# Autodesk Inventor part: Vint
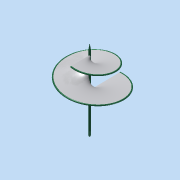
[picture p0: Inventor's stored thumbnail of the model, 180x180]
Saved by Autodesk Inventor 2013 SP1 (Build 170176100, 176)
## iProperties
Created: 2016-04
Part Number: Vint
Material: Пластик АБС
Document SubType Name: Modeling
Designer: Кравец
Density: 1 g/cm^3
Author: Кравец
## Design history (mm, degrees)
sketch "Эскиз1"
  geometry: L1 (0, 0)-(0, 70)
  constraints: 2 end point, 1 vertical
  dimensions: "d0" = 70 distance of L1.start L1.end
node "3D-эскиз3"
sketch "3D-эскиз4"
feature "Участок поверхности1" sketch "3D-эскиз4" dims "d17" = 0
feature "Толщина1" dims "d18" = 1, "d19" = 1
sketch "Эскиз2"
  geometry: L1 (0, 0)-(0, 80); L2 (-45, 80)-(-75, 0); L3 (-75, 0)-(-101.109, 0); L4 (-101.109, 0)-(-101.996, 80); L5 (-101.996, 80)-(-45, 80)
  constraints: 10 end point, 2 horizontal, 2 point on line, 1 vertical
  dimensions: "d20" = 80 vertical distance of L3.end L4.end; "d22" = 150 diameter of L2.end L1; "d23" = 90 diameter of L2.start L1
revolve "Вращение1" sketch "Эскиз2" stored, may be unused: angle "d24" = 90 deg
node "РабПлоскость1"
sketch "Эскиз3"
  geometry: C1 r 1.5 at (0, 0); 1 further point
  constraints: 1 centre point
  dimensions: "d25" = 3 diameter of C1
sketch "3D-эскиз5"
feature "Сдвиг1" sketch "Эскиз3", "3D-эскиз5" dims "d27" = 0
sketch "Эскиз4"
  geometry: L1 (0, 100)-(-2.5, 85); L2 (-2.5, -95)-(0, -95); L3 (0, 100)-(0, -95); L4 (-2.5, -2)-(-5, -2); L5 (-5, -2)-(-5, -3); L6 (-5, -3)-(-4, -3); L7 (-2.5, 85)-(-2.5, -2); L8 (-2.5, -6)-(-2.5, -95); L9 (-4, -3)-(-4, -6); L10 (-4, -6)-(-2.5, -6); 1 further point
  constraints: 20 end point, 5 perpendicular, 3 parallel, 1 point on line
  dimensions: "d30" = 100 distance of point (0, 0) L1.start; "d31" = 15 vertical distance of L1.start L1.end; "d32" = 180 distance of L1.end L2.start; "d36" = 1 distance between parallel lines of L6 L4; "d37" = 10 diameter of L5 L3; "d38" = 2 distance from line of point (0, 0) L4; "d44" = 5 diameter of L7 L3; "d45" = 5 diameter of L8 L3; "d46" = 8 diameter of L9 L3; "d47" = 3 distance of L6.end L9.end
revolve "Вращение2" sketch "Эскиз4" stored, may be unused: angle "d33" = 90 deg
fillet "Сопряжение1" dims "d34" = 15
sketch "Эскиз5"
  geometry: C1 r 2.5 at (0, 0) reference; C2 r 1.5 at (0, 0)
  constraints: 1 centre point, 1 coincident
  dimensions: "d39" = 3 diameter of C2
extrude "Выдавливание1" cut sketch "Эскиз5" distance "d41" = 2; taper "d42" = 0 deg
fillet "Сопряжение2" dims "d43" = 0.5
sketch "Эскиз6"
  geometry: L1 (-1.5, 2)-(-1.5, -2); A1 r 2.5 centre (0, 0) between (-1.5, 2) and (-1.5, -2) reference
  constraints: 2 end point, 2 point on circle, 1 vertical
extrude "Выдавливание2" cut sketch "Эскиз6" distance "d48" = 10; taper "d49" = 0 deg
node "Твердое тело1"
node "Спираль3" dims "d9" = 50, "d10" = 15, "d11" = 150, "d12" = 0
node "Спираль4" dims "d13" = 50, "d14" = 15, "d15" = 2, "d16" = 0
body "SRF1"
node "Твердое тело2"
other parameters: "d35" = 5
